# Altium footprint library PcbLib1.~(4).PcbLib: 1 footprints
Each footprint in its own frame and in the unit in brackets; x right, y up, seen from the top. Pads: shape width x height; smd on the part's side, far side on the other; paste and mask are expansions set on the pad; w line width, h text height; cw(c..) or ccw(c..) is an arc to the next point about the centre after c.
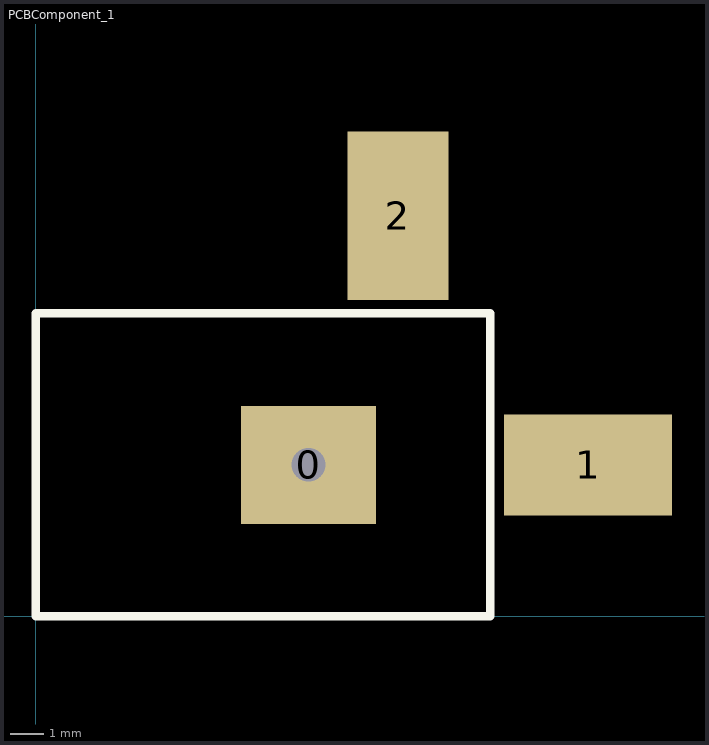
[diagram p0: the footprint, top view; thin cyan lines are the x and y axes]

## PCBComponent_1 [mm]
pads (3):
  rect 4x3.5 hole 1 square: 0(8.1,4.5)
  rect 5x3 all layers, no hole: 1(16.4,4.5)
  rect 3x5 all layers, no hole: 2(10.75,11.9)
Top Overlay:
  lines w0.254: 0,0 0,9 13.5,9 13.5,0 0,0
